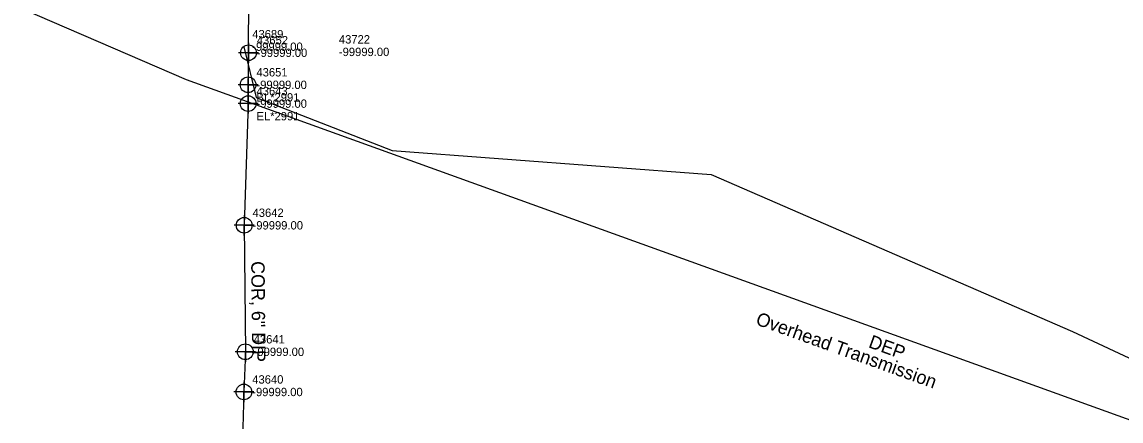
# Model space of a CAD drawing. Extents: x 2083698 to 2094313, y 743246 to 752873.
# Drawn here: x 2092141.2 to 2092469.5, y 747070.2 to 747189.5 of the extents above; entities that cross this region are included whole.
import ezdxf

# ---------------------------------------------------------------- set-up
doc = ezdxf.new("R2010")
doc.units = 0
for name, color, linetype in [('COGO Default Point Number', 7, 'Continuous'), ('Exist Property Line', 7, 'Continuous'), ('Exist Right of Way Line', 7, 'Continuous'), ('Exist Right of Way Width CELL', 7, 'Continuous'), ('Exist Utilities Power Joint Use Telephone Cogo Elevation', 7, 'Continuous'), ('Exist Utilities Power Joint Use Telephone Cogo Number', 7, 'Continuous'), ('Exist Utilities Power UG Cable SUE LOS C', 7, 'Continuous'), ('Exist Utilities Power UG Cable SUE LOS C Text', 7, 'Continuous'), ('Exist Utilities Telephone UG Cable SUE LOS C', 7, 'Continuous'), ('Exist Utilities Water UG Line SUE LOS B', 7, 'Continuous'), ('Exist Utilities Water UG Line SUE LOS B Text', 7, 'Continuous')]:
    doc.layers.add(name, color=color, linetype=linetype)

msp = doc.modelspace()

# ---------------------------------------------------------------- linework, layer by layer
at = {"layer": 'COGO Default Point Number'}
for points in [[(2092208.89, 747183.26), (2092208.89, 747177.26), (2092208.89, 747180.26), (2092211.89, 747180.26), (2092205.89, 747180.26)], [(2092208.77, 747173.68), (2092208.77, 747167.68), (2092208.77, 747170.68), (2092211.77, 747170.68), (2092205.77, 747170.68)], [(2092208.79, 747168.06), (2092208.79, 747162.06), (2092208.79, 747165.06), (2092211.79, 747165.06), (2092205.79, 747165.06)], [(2092207.61, 747131.69), (2092207.61, 747125.69), (2092207.61, 747128.69), (2092210.61, 747128.69), (2092204.61, 747128.69)], [(2092207.95, 747093.88), (2092207.95, 747087.88), (2092207.95, 747090.88), (2092210.95, 747090.88), (2092204.95, 747090.88)], [(2092207.52, 747081.88), (2092207.52, 747075.88), (2092207.52, 747078.88), (2092210.52, 747078.88), (2092204.52, 747078.88)]]:
    msp.add_lwpolyline(points, dxfattribs=at)
for centre in [(2092208.89, 747180.26), (2092208.77, 747170.68), (2092208.79, 747165.06), (2092207.61, 747128.69), (2092207.95, 747090.88), (2092207.52, 747078.88)]:
    msp.add_circle(centre, 2.34, dxfattribs=at)
at = {"layer": 'Exist Utilities Power UG Cable SUE LOS C'}
msp.add_lwpolyline([(2091387.72, 747754.05), (2091459.29, 747488.14), (2091734.16, 747369.44), (2092190.29, 747172.26), (2092598.52, 747024.9), (2092972.51, 746889.78), (2093316.78, 746787.16), (2093711.24, 746532.37)], dxfattribs=at)
at = {"layer": 'Exist Utilities Telephone UG Cable SUE LOS C'}
msp.add_lwpolyline([(2092207.52, 747182.07), (2092211.14, 747166.84), (2092251.83, 747151.07), (2092347.09, 747143.88), (2092454.99, 747097), (2092528.67, 747062.49), (2092609.5, 747024.14), (2092621.64, 747029.87), (2092634.52, 747091.34)], dxfattribs=at)
at = {"layer": 'Exist Utilities Water UG Line SUE LOS B'}
for points in [[(2092208.79, 747165.06), (2092208.89, 747180.26), (2092209.04, 747197.21)], [(2092208.79, 747165.06), (2092207.61, 747128.69), (2092207.95, 747090.88), (2092207.52, 747078.88), (2092207.02, 747061), (2092206.37, 747047.06), (2092207.24, 747021.83), (2092205.72, 747014.02)]]:
    msp.add_lwpolyline(points, dxfattribs=at)

# ---------------------------------------------------------------- texts
at = {"layer": 'Exist Property Line'}
for p in [(2092211.39, 747179.01), (2092211.27, 747169.43), (2092211.29, 747163.81), (2092210.11, 747127.44), (2092210.45, 747089.63), (2092210.02, 747077.63)]:
    msp.add_text('-99999.00', height=2.5, dxfattribs=at).set_placement(p)
at = {"layer": 'Exist Right of Way Line'}
for s, p in [('43652', (2092211.39, 747182.76)), ('43651', (2092211.27, 747173.18)), ('43643', (2092211.29, 747167.56)), ('43642', (2092210.11, 747131.19)), ('43641', (2092210.45, 747093.38)), ('43640', (2092210.02, 747081.38))]:
    msp.add_text(s, height=2.5, dxfattribs=at).set_placement(p)
at = {"layer": 'Exist Right of Way Width CELL'}
for s, p in [('BL*2991', (2092211.27, 747165.68)), ('EL*2991', (2092211.29, 747160.06))]:
    msp.add_text(s, height=2.5, dxfattribs=at).set_placement(p)
at = {"layer": 'Exist Utilities Power Joint Use Telephone Cogo Elevation'}
for p in [(2092210.02, 747180.82), (2092235.89, 747179.27)]:
    msp.add_text('-99999.00', height=2.5, dxfattribs=at).set_placement(p)
at = {"layer": 'Exist Utilities Power Joint Use Telephone Cogo Number'}
for s, p in [('43689', (2092210.02, 747184.57)), ('43722', (2092235.89, 747183.02))]:
    msp.add_text(s, height=2.5, dxfattribs=at).set_placement(p)
at = {"layer": 'Exist Utilities Power UG Cable SUE LOS C Text'}
for s, p in [('Overhead Transmission', (2092360.12, 747099.13)), ('DEP', (2092393.81, 747092.29))]:
    msp.add_text(s, height=4, rotation=340.1514, dxfattribs=at).set_placement(p)
at = {"layer": 'Exist Utilities Water UG Line SUE LOS B Text'}
msp.add_text('COR, 6" DIP', height=4, rotation=270.5167, dxfattribs=at).set_placement((2092209.7, 747117.96))

doc.saveas('drawing.dxf')
